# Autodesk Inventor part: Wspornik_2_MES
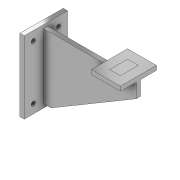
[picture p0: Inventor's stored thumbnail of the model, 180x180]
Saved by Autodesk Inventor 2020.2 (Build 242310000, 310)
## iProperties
Created: 2017-03
Part Number: Wspornik_2_MES
Material: Stal
Document SubType Name: Modeling
Designer: F.Stasiak
Density: 7.85 g/cm^3
Appearance: Chrom — polerowany
Mass: 5930.83 g
Surface Area: 1409.61 cm^2
Volume: 755.52 cm^3
Catalog Web Link: www.expertbooks.pl
Manager: www.cadconsulting.pl
Company: Fabian Stasiak CAD Consulting
Author: F.Stasiak
Subject: Zbiór ćwiczeń. Autodesk Inventor 2020. Kurs Professional
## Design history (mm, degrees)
sketch "Szkic3"
  geometry: L1 (-12, 0)-(0, 0); L2 (0, 0)-(0, -200); L3 (0, -200)-(-12, -200); L4 (-12, -200)-(-12, 0); L5 (-12, -10)-(-268, -10); L6 (-268, -10)-(-268, -50); L7 (-268, -50)-(-32, -190); L8 (-32, -190)-(-12, -190); L9 (-268, -10)-(-167.827, -10); L10 (-256, -22)-(-268, -10); L11 (-268, -10)-(-188, -10); L12 (-188, -10)-(-188, 2); L13 (-188, 2)-(-268, 2); L14 (-268, 2)-(-268, -10); 1 further point
  constraints: 28 end point, 4 horizontal, 4 parallel, 4 perpendicular, 2 point on line, 1 coincident
  dimensions: "d4" = 12 distance of L2.end L3.end; "d5" = 200 distance of L1.end L2.end; "d6" = 256 distance of L5.start L5.end; "d7" = 10 distance between parallel lines of L1 L5; "d8" = 10 distance between parallel lines of L3 L8 (= d7); "d9" = 40 distance of L5.end L6.end; "d10" = 20 distance of L7.end L8.end; "d19" = 80 distance of L13.end L12.end; "d20" = 12 distance of L12.end L11.end
extrude "Wyciągnięcie proste3" new body sketch "Szkic3" stored distance "d13" = 120; taper "d14" = 0 deg
extrude "Wyciągnięcie proste4" join sketch "Szkic3" stored distance "d15" = 12; taper "d16" = 0 deg
extrude "Wyciągnięcie proste5" join sketch "Szkic3" stored distance "d17" = 100; taper "d18" = 0 deg
sketch "Szkic6"
  geometry: L1 (0, 0)-(0, 120) reference; L2 (-200, 120)-(0, 120) reference; L3 (-200, 0)-(-200, 120) reference; L4 (0, 0)-(-200, 0) reference; L5 (-175, 25)-(-175, 95); L6 (-175, 95)-(-25, 95); L7 (-25, 95)-(-25, 25); L8 (-25, 25)-(-175, 25); 5 further points
  constraints: 8 end point, 4 coincident, 3 other
  dimensions: "d28" = 25 distance between parallel lines of L4 L8
hole "Otwór1" sketch "Szkic6" at (-25, 95), (-25, 25), (-175, 95), (-175, 25) diameter "d29" = 12; stored, may be unused: countersink angle "d33" = 90 deg, drill point angle "d35" = 118 deg; dims "d30" = 6, "d31" = 4, "d32" = 2, "d34" = 8
sketch "Szkic7"
  geometry: L1 (80, -100)-(80, 0) reference; L2 (0, 0)-(80, 0) reference; L3 (0, -100)-(0, 0) reference; L4 (80, -100)-(0, -100) reference; L5 (55, -25)-(55, -75); L6 (55, -75)-(25, -75); L7 (25, -75)-(25, -25); L8 (25, -25)-(55, -25); 1 further point
  constraints: 8 end point, 3 other
  dimensions: "d36" = 25 distance between parallel lines of L2 L8
feature "Podział1" sketch "Szkic7"
node "Bryła3"
node "Pętla rzutowana2"
node "Pętla rzutowana3"
